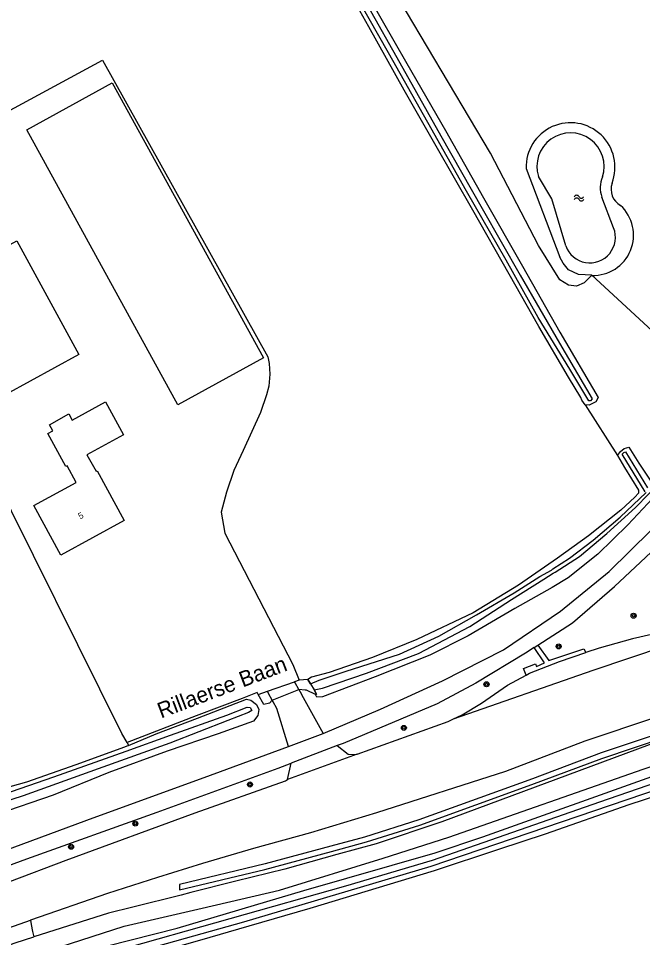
# Model space of a CAD drawing. Extents: x 126000 to 131009, y 393000 to 395500.
# Drawn here: x 130267.3 to 130366.9, y 393445.3 to 393591.8 of the extents above; entities that cross this region are included whole.
import ezdxf

# ---------------------------------------------------------------- set-up
doc = ezdxf.new("R2010")
doc.units = 0
for name, color, linetype in [('gg-afsc-hekwerk', 7, 'Continuous'), ('gg-afsc-lijn haag', 7, 'Continuous'), ('gg-anno-huisnummerreeks BGT', 7, 'Continuous'), ('gg-anno-openbare ruimte label', 7, 'Continuous'), ('gg-bbg-bijgebouw', 7, 'Continuous'), ('gg-bbg-hoofdgebouw', 7, 'Continuous'), ('gg-knt-bronhoudergrens', 7, 'Continuous'), ('gg-kntw-bovenkant insteek waterloop', 7, 'Continuous'), ('gg-kntw-waterlijn', 7, 'Continuous'), ('gt-symb-boom', 7, 'Continuous'), ('gt-symb-watersymbool', 7, 'Continuous'), ('gx-grn-maaiveld', 7, 'Continuous')]:
    doc.layers.add(name, color=color, linetype=linetype)

# ---------------------------------------------------------------- blocks, each defined once
blk = doc.blocks.new('gt0-WA')
at = {"layer": 'gt-symb-watersymbool'}
for centre, start, end in [((-0.32, 0.02), 28.0725, 151.9275), ((0.43, 0.42), 208.0725, 331.9275), ((-0.32, -0.43), 28.0725, 151.9275), ((0.43, -0.03), 208.0725, 331.9275)]:
    blk.add_arc(centre, 0.425, start, end, dxfattribs=at)
blk = doc.blocks.new('gt0-BOOM')
at = {"layer": 'gt-symb-boom'}
for radius in [0.4, 0.2]:
    blk.add_circle((0, 0), radius, dxfattribs=at)

msp = doc.modelspace()

# ---------------------------------------------------------------- linework, layer by layer
at = {"layer": 'gg-afsc-hekwerk'}
msp.add_lwpolyline([(130313.52, 393486.42), (130313.92, 393485.76), (130314.49, 393484.81), (130314.9, 393484.13), (130314.72, 393484.03)], dxfattribs=at)
at = {"layer": 'gg-afsc-lijn haag'}
for points in [[(130306.47, 393482.44), (130305.59, 393484.07), (130305.43, 393484.36), (130303.03, 393483.44), (130295.7, 393480.66)], [(130295.7, 393480.66), (130284.67, 393476.38), (130283.85, 393477.84)]]:
    msp.add_lwpolyline(points, dxfattribs=at)
at = {"layer": 'gg-bbg-bijgebouw'}
for p, q in [((130268.69, 393574.05), (130282.3, 393581.55)), ((130282.3, 393581.55), (130306.42, 393537.71))]:
    msp.add_line(p, q, dxfattribs=at)
for points in [[(130306.42, 393537.71), (130292.78, 393530.22), (130268.69, 393574.05)], [(130255.41, 393550), (130267.06, 393556.37), (130276.97, 393538.26), (130265.33, 393531.89), (130255.41, 393550)]]:
    msp.add_lwpolyline(points, dxfattribs=at)
at = {"layer": 'gg-bbg-hoofdgebouw'}
msp.add_lwpolyline([(130269.78, 393514.15), (130276.53, 393517.86), (130275.09, 393520.49), (130274.91, 393520.39), (130272.02, 393525.65), (130272.81, 393526.09), (130272.28, 393527.05), (130275.4, 393528.76), (130275.93, 393527.8), (130281.23, 393530.71), (130284.12, 393525.46), (130278.24, 393522.23), (130279.75, 393519.64), (130279.88, 393519.7), (130284.2, 393511.81), (130274.12, 393506.27), (130269.78, 393514.15)], dxfattribs=at)
at = {"layer": 'gg-knt-bronhoudergrens'}
msp.add_lwpolyline([(130246.15, 393566.4), (130266.72, 393577.56), (130280.75, 393585.17)], dxfattribs=at)
at = {"layer": 'gg-kntw-bovenkant insteek waterloop'}
msp.add_lwpolyline([(130284.9, 393475.94), (130284.27, 393475.68), (130276.5, 393472.84), (130268.62, 393470.09), (130262.91, 393468.51), (130257.64, 393466.69)], dxfattribs=at)
for centre, radius, start, end in [((130355.39, 393568.09), 7.09, 338.9707, 181.7918), ((130364.81, 393564.57), 2.96, 160.8069, 240.6304), ((130359.04, 393557.26), 6.41, 267.6721, 47.6614)]:
    msp.add_arc(centre, radius, start, end, dxfattribs=at)
at = {"layer": 'gg-kntw-waterlijn'}
msp.add_line((130362.27, 393558.41), (130360.37, 393563.33), dxfattribs=at)
for points in [[(130354.64, 393555.54), (130352.4, 393563.03), (130350.27, 393566.6)], [(130252.73, 393463.63), (130253.56, 393463.89), (130257.39, 393465.18), (130263.58, 393467.68), (130273.01, 393470.94), (130284.52, 393475.03), (130291.61, 393477.56), (130300.56, 393480.77), (130303.8, 393482.05), (130304.32, 393481.98), (130304.54, 393481.52), (130304.05, 393481.17), (130300.74, 393479.9), (130291.49, 393476.28), (130280.08, 393472.22), (130268.09, 393467.89), (130257.81, 393464.59), (130252.91, 393462.58)]]:
    msp.add_lwpolyline(points, dxfattribs=at)
for centre, radius, start, end in [((130355.39, 393568.19), 5.37, 342.0468, 197.1803), ((130364.34, 393564.78), 4.22, 155.4393, 200.0181), ((130358.47, 393556.92), 4.08, 199.7907, 21.453)]:
    msp.add_arc(centre, radius, start, end, dxfattribs=at)
at = {"layer": 'gx-grn-maaiveld'}
for p, q in [((130280.75, 393585.17), (130307.11, 393537.86)), ((130348.3, 393567.87), (130353.69, 393553.73)), ((130357.74, 393530.2), (130362.86, 393522.17)), ((130349.59, 393491.55), (130350.16, 393491.92)), ((130307.06, 393484.58), (130311.38, 393486.07)), ((130312.1, 393486.32), (130311.38, 393486.07)), ((130313.52, 393486.42), (130312.1, 393486.32)), ((130313.92, 393485.76), (130313.52, 393486.42)), ((130313.92, 393485.76), (130314.49, 393484.81)), ((130305.59, 393484.07), (130307.06, 393484.58)), ((130307.82, 393483.14), (130312.04, 393484.86)), ((130310.42, 393475.79), (130315.93, 393477.84)), ((130284.67, 393476.38), (130284.9, 393475.94)), ((130318.18, 393475.91), (130310.86, 393473.09)), ((130321.36, 393474.52), (130310.23, 393470.5)), ((130310.23, 393470.5), (130310.86, 393473.09)), ((130263.39, 393446.04), (130269.25, 393448.08))]:
    msp.add_line(p, q, dxfattribs=at)
for points in [[(130358.78, 393550.86), (130357.56, 393549.64), (130356.34, 393549.12), (130355.07, 393549.29), (130353.71, 393550.16), (130350.27, 393555.59), (130342.63, 393570.32), (130305.79, 393632.33), (130304.48, 393637.56), (130303.47, 393642.64), (130298.53, 393651.21), (130287.98, 393668.92)], [(130357.74, 393530.2), (130357.19, 393530.98), (130357.02, 393531.4), (130355.09, 393534.65), (130350.34, 393542.71), (130345.61, 393551.03), (130339.79, 393561.24), (130333.96, 393571.45), (130328.88, 393580.38), (130323.25, 393590.44), (130316.99, 393601.59)], [(130358.59, 393530.87), (130358.33, 393530.86), (130355.26, 393535.9), (130350.24, 393544.15), (130345.12, 393553.3), (130338.82, 393564.26), (130332.62, 393575.23), (130326.35, 393586.33), (130320, 393597.58)], [(130322.55, 393594.69), (130328.67, 393583.85), (130334.69, 393573.11), (130341.29, 393561.49), (130347.34, 393550.89), (130353.62, 393540.07), (130358.85, 393531.17), (130358.59, 393530.87)], [(130323.09, 393595.52), (130329.28, 393584.6), (130335.44, 393573.95), (130341.49, 393563.19), (130347.72, 393552.3), (130353.68, 393541.79), (130359.82, 393531.39), (130359.44, 393530.69), (130358.34, 393530.16), (130357.74, 393530.2)], [(130284.67, 393476.38), (130283.85, 393477.84), (130262.68, 393520.32), (130262.41, 393521.85), (130262.49, 393523.46), (130262.83, 393524.48), (130263.63, 393525.47), (130264.56, 393526.49), (130265.65, 393527.87), (130265.95, 393528.49), (130265.99, 393528.95), (130265.84, 393529.4), (130265.34, 393530.29), (130262.03, 393536.53), (130253.01, 393553.1), (130246.15, 393566.4)], [(130358.78, 393550.86), (130370.49, 393540.08), (130376.57, 393546.3), (130381.6, 393555.43), (130386.36, 393561.65), (130390.86, 393564.03), (130396.15, 393560.85), (130399.85, 393556.13)], [(130358.78, 393550.86), (130356.65, 393551.01), (130355.07, 393551.74), (130354.22, 393552.77), (130353.69, 393553.73)], [(130362.86, 393522.17), (130363.38, 393522.77), (130363.95, 393523.24), (130364.69, 393523.49), (130366.27, 393520.94), (130368.08, 393518.2), (130369.88, 393520.21), (130373.17, 393523.17), (130373.22, 393523.22), (130374.15, 393524.14), (130393.47, 393546.93), (130396.36, 393550.34)], [(130314.49, 393484.81), (130315.84, 393485.05), (130322.85, 393487.45), (130331.17, 393490.6), (130339.32, 393494.91), (130345.97, 393499.18), (130351.12, 393502.41), (130352.62, 393503.38), (130352.96, 393503.57), (130356.82, 393506.05), (130361.2, 393509.73), (130365.75, 393513.87), (130367.81, 393515.96), (130368.4, 393516.55), (130371.33, 393519.63), (130383.18, 393531.19), (130397.84, 393549.02)], [(130398.46, 393548.47), (130384.24, 393530.83), (130383.96, 393530.49), (130380.53, 393526.23), (130371.56, 393518.6), (130367.7, 393514.47), (130364.51, 393511.11), (130359.73, 393506.42), (130355.03, 393502.65), (130352.44, 393501.1), (130346.51, 393497.77), (130339.05, 393493.42), (130332.94, 393490.32), (130324.22, 393486.89), (130315.85, 393483.68), (130314.95, 393483.61), (130314.72, 393484.03)], [(130315.93, 393477.84), (130325.11, 393481.7), (130334.96, 393486.24), (130344.7, 393491.19), (130353.78, 393497.31), (130361.57, 393503.67), (130368.22, 393510.17), (130373.82, 393516.64), (130380.79, 393524.45), (130384.85, 393529.69), (130399.36, 393547.68)], [(130350.16, 393491.92), (130355.71, 393495.48), (130362.41, 393501.26), (130369.06, 393507.47), (130373.27, 393512.04), (130378.98, 393519.37), (130384.43, 393525.82), (130386.4, 393528.3), (130399.27, 393544.38), (130399.67, 393544.27)], [(130307.11, 393537.86), (130307.35, 393536.81), (130307.43, 393535.08), (130307.29, 393533.22), (130306.91, 393531.81), (130305.93, 393529.02), (130303.16, 393522.93), (130301.69, 393519.75), (130300.52, 393516.31), (130299.67, 393513.09), (130300.26, 393509.79), (130311.12, 393488.82), (130312.1, 393486.32)], [(130367.28, 393516.36), (130363.64, 393522.34), (130363.89, 393522.61), (130364.18, 393522.71), (130367.67, 393516.97)], [(130362.86, 393522.17), (130364, 393520.22), (130366.24, 393516.63), (130366.24, 393516.14), (130365.63, 393515.5), (130363.4, 393513.42), (130358.26, 393509.36), (130353.31, 393505.76), (130347.12, 393501.49), (130339.89, 393497.09), (130330.87, 393492.84), (130323.81, 393489.95), (130316.91, 393487.54), (130314.09, 393486.81), (130313.52, 393486.42)], [(130313.92, 393485.76), (130315.31, 393486.33), (130319.61, 393487.75), (130328.11, 393490.48), (130334.39, 393493.33), (130340.4, 393496.77), (130346.42, 393500.27), (130350.48, 393502.88), (130352.34, 393503.86), (130352.57, 393504.07), (130355.24, 393505.77), (130359.01, 393508.64), (130363.31, 393512.31), (130367.43, 393516.24)], [(130336.75, 393480.17), (130358.98, 393487.95), (130387.92, 393497.67)], [(130387.92, 393497.67), (130380.51, 393495.74), (130373.18, 393494.75), (130365.29, 393492.92), (130359.97, 393491.46), (130357.85, 393490.74)], [(130349.59, 393491.55), (130348.19, 393490.66), (130340.29, 393485.88), (130334.13, 393482.59), (130319.11, 393476.27), (130318.18, 393475.91)], [(130348.29, 393487.13), (130347.88, 393488.18), (130349.79, 393488.92), (130349.98, 393488.52), (130351.26, 393489.12), (130349.59, 393491.55)], [(130350.16, 393491.92), (130351.94, 393489.46), (130357.51, 393491.34), (130357.85, 393490.74)], [(130408.42, 393490.67), (130398.02, 393487.35), (130380.57, 393481.52), (130360.29, 393474.74), (130349.35, 393470.64), (130331.21, 393464.07), (130322.54, 393461.34), (130317.18, 393459.9), (130306.68, 393457.07), (130293.05, 393453.8), (130293.04, 393453.26), (130293.03, 393452.92), (130306.62, 393456.18), (130317.25, 393459.05), (130322.86, 393460.56), (130331.38, 393463.24), (130349.21, 393469.7), (130360.37, 393473.88), (130380.92, 393480.75), (130398.23, 393486.53), (130409.2, 393490.03)], [(130348.29, 393487.13), (130348.85, 393487.43), (130353.65, 393489.31), (130357.85, 393490.74)], [(130408.92, 393489.53), (130408.46, 393489.42), (130397.28, 393485.86), (130367.91, 393476.04), (130334.89, 393463.75), (130324.38, 393460.28), (130318.11, 393458.55), (130309.85, 393456.24), (130302, 393454.3), (130294.84, 393452.48), (130293.31, 393452.09), (130285.56, 393450.14), (130281.71, 393449.23), (130269.78, 393445.43)], [(130391.48, 393487.95), (130357.65, 393476.6), (130345.04, 393471.8), (130324.47, 393465.2), (130313.91, 393461.99), (130304.85, 393459.51), (130296.72, 393457.13), (130289.51, 393454.88), (130281.54, 393452.36), (130269.25, 393448.08)], [(130255.31, 393436.79), (130267.24, 393441.65), (130284.19, 393447.11), (130296.64, 393449.98), (130309, 393452.86), (130325.51, 393457.97), (130335.97, 393461.31), (130366.98, 393472.14), (130388.38, 393479.36), (130407.42, 393485.78), (130411.15, 393486.82)], [(130312.04, 393484.86), (130311.46, 393485.92), (130311.38, 393486.07)], [(130336.75, 393480.17), (130338.13, 393480.8), (130341.2, 393482.67), (130345.35, 393485.53), (130348.29, 393487.13)], [(130305.59, 393484.07), (130305.43, 393484.36), (130303.03, 393483.44), (130295.7, 393480.66), (130284.67, 393476.38)], [(130307.82, 393483.14), (130307.24, 393484.23), (130307.06, 393484.58)], [(130314.72, 393484.03), (130313.29, 393484.74), (130313.09, 393484.76), (130312.04, 393484.86)], [(130312.04, 393484.86), (130312.26, 393484.46), (130312.73, 393483.6), (130315.93, 393477.84)], [(130314.72, 393484.03), (130314.9, 393484.13), (130314.49, 393484.81)], [(130284.9, 393475.94), (130289.33, 393477.77), (130295.9, 393480.27), (130303.69, 393483.29), (130304.42, 393483.13), (130305.31, 393482.45), (130305.67, 393481.69), (130305.53, 393480.69), (130304.82, 393479.83), (130299.2, 393477.79), (130291.06, 393475.05), (130281.78, 393471.65), (130272.9, 393467.99), (130263.82, 393464.92), (130256.75, 393462.38), (130253.42, 393460.98), (130251.7, 393460.2), (130250.82, 393459.72), (130250.32, 393459.28), (130250.08, 393458.95), (130249.9, 393458.41), (130249.85, 393457.93), (130249.94, 393457.11), (130250.59, 393454.18)], [(130276.69, 393442.56), (130281.52, 393444.01), (130292.64, 393446.8), (130312.86, 393452.82), (130333.8, 393458.82), (130341.39, 393461.36), (130369.84, 393471.5), (130388.56, 393478.22), (130408.5, 393484.17), (130409.36, 393484.17), (130410.17, 393484.07), (130410.71, 393483.49), (130410.77, 393483.26), (130410.88, 393482.8), (130410.84, 393481.81), (130410.25, 393481.41)], [(130277.37, 393440.27), (130282.97, 393442.12), (130303.31, 393447.8), (130333.19, 393456.71), (130369.58, 393469.08), (130389.49, 393475.92), (130408.86, 393481.66), (130409.95, 393482.64), (130409.86, 393482.87), (130409.8, 393482.95), (130409.71, 393483.07), (130409.48, 393483.11), (130409.09, 393483.13), (130408.36, 393482.99), (130381.41, 393474.27), (130360, 393466.9), (130333.3, 393457.62), (130319.48, 393453.52), (130282.59, 393443.1), (130277.03, 393441.41)], [(130307.82, 393483.14), (130307.39, 393482.66), (130306.47, 393482.44), (130305.59, 393484.07)], [(130310.42, 393475.79), (130308.53, 393481.82), (130307.97, 393482.87), (130307.82, 393483.14)], [(130410.25, 393481.41), (130409.27, 393480.88), (130404.67, 393479.53), (130391.89, 393475.43), (130377.54, 393470.65), (130364.68, 393466.48), (130351.36, 393461.82), (130343.93, 393459.37), (130333.63, 393455.97), (130313.83, 393449.96), (130304.09, 393447.13), (130296.24, 393444.86), (130282.28, 393440.93), (130277.63, 393439.41)], [(130321.36, 393474.52), (130335.86, 393479.77), (130336.75, 393480.17)], [(130250.59, 393454.18), (130265.32, 393459.25), (130279.26, 393464.39), (130296.98, 393470.83), (130310.42, 393475.79)], [(130318.18, 393475.91), (130319.93, 393474.54), (130320.67, 393474.51), (130321.36, 393474.52)], [(130251.5, 393451.29), (130256.1, 393453.23), (130268.68, 393457.84), (130289.48, 393465.29), (130308.79, 393472.3), (130310.86, 393473.09)], [(130251.72, 393448.94), (130256.95, 393450.85), (130274.97, 393457.65), (130295.53, 393465.18), (130309.91, 393470.31), (130310.23, 393470.5)], [(130269.25, 393448.08), (130269.38, 393447.42), (130269.6, 393446.31), (130269.78, 393445.43)], [(130264.13, 393443.54), (130266.83, 393444.49), (130269.78, 393445.43)]]:
    msp.add_lwpolyline(points, dxfattribs=at)

# ---------------------------------------------------------------- block references
at = {"layer": 'gt-symb-boom'}
for p in [(130365.45, 393496.61), (130353.5, 393491.72), (130341.99, 393485.69), (130328.81, 393478.74), (130304.27, 393469.71), (130285.98, 393463.47), (130275.73, 393459.78)]:
    msp.add_blockref('gt0-BOOM', p, dxfattribs=at)
at = {"layer": 'gt-symb-watersymbool', "rotation": 180}
msp.add_blockref('gt0-WA', (130356.8, 393563.16), dxfattribs=at)

# ---------------------------------------------------------------- texts
at = {"layer": 'gg-anno-huisnummerreeks BGT'}
msp.add_text('5', height=1, rotation=28.8, dxfattribs=at).set_placement((130277.19, 393511.95))
at = {"layer": 'gg-anno-openbare ruimte label'}
msp.add_text('Rillaerse Baan', height=2.5, rotation=20.8, dxfattribs=at).set_placement((130290.09, 393480.21))

doc.saveas('drawing.dxf')
